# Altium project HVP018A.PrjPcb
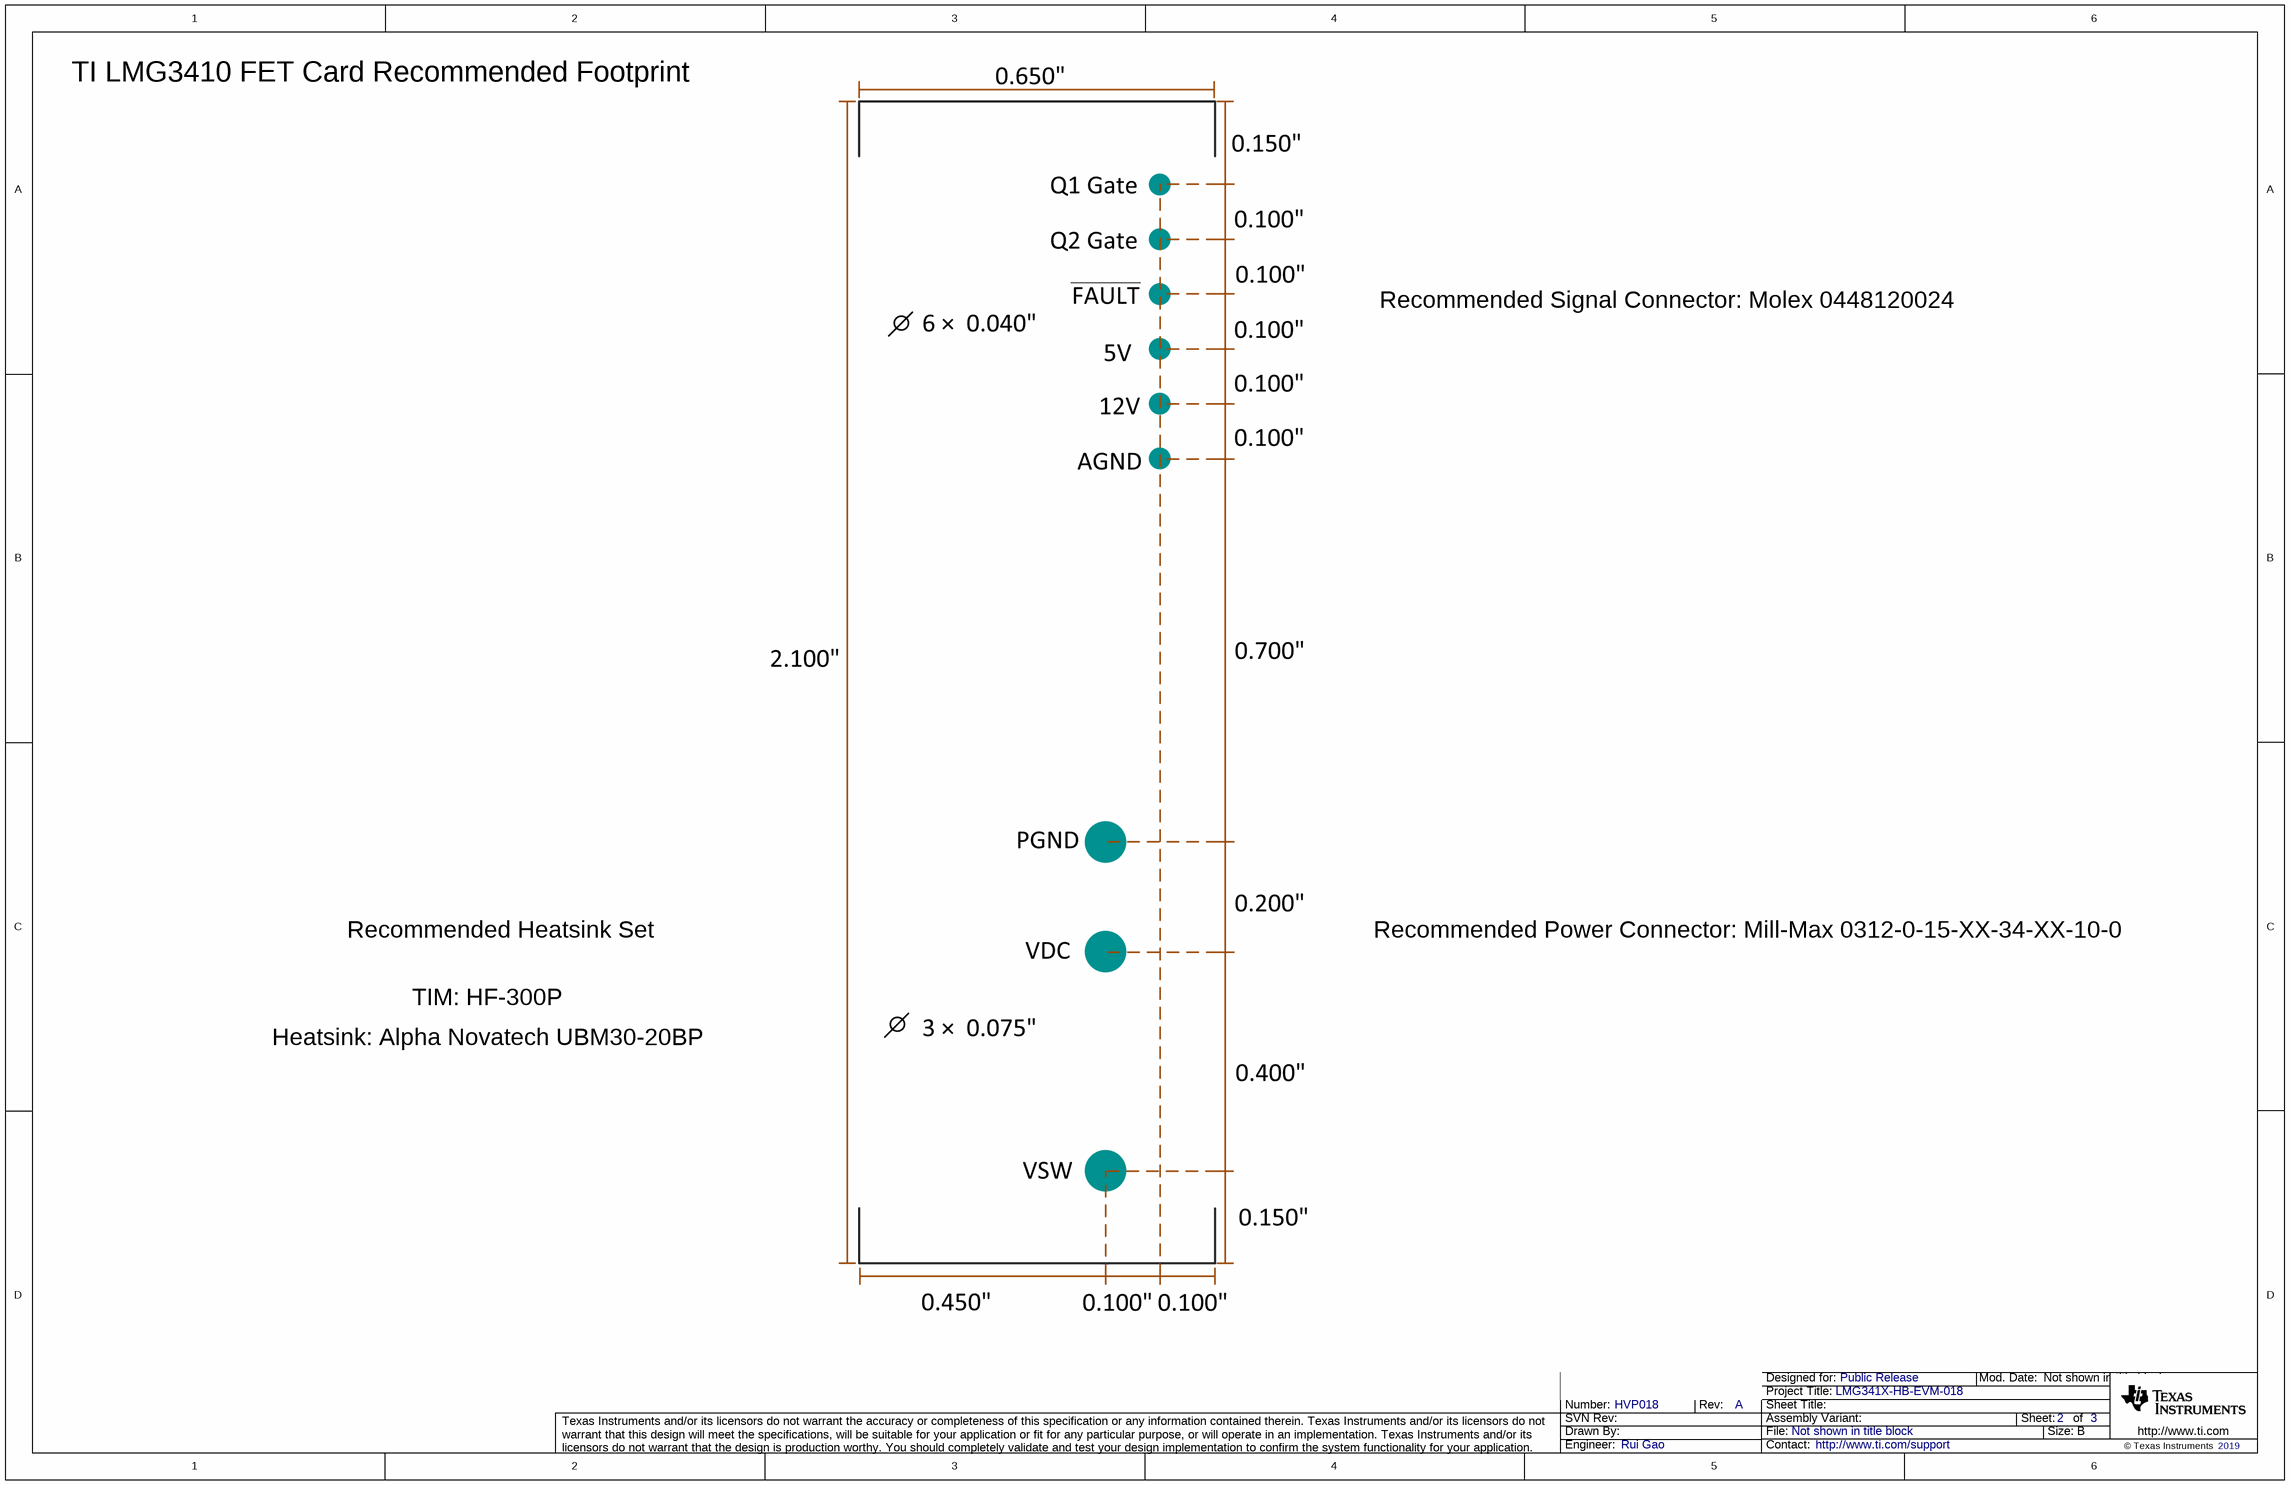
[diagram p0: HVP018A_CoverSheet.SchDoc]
CopyrightYear: 2019; PCB_Layout: Rui Gao; PCB_Rev: A; PRJ_Customer: Public Release; PRJ_Engineer: Rui Gao; PRJ_Number: HVP018; PRJ_Title: LMG341X-HB-EVM-018; SCH_Rev: A; TechSupport: http://www.ti.com/support; TID: N/A
3 sheets, 98 parts. Net scope: global (net labels, ports and power ports of the same name join across sheets).
Board file: HVP018A.PcbDoc
Sheets:
  HVP018A_CoverSheet.SchDoc
  HVP018A_DC.SchDoc
  HVP018A_Hardware.SchDoc

## Sheet HVP018A_CoverSheet.SchDoc
size 431 x 279 mm; Date: Not shown in title block; ApprovedBy: Not shown in title block; CheckedBy: Not shown in title block; Author: Not shown in title block; CompanyName: Not shown in title block; Engineer: Not shown in title block; Organization: Not shown in title block; Address1: Not shown in title block; Address2: Not shown in title block; Address3: Not shown in title block; Address4: Not shown in title block; DocumentNumber: 1; Revision: Use project parameter SCH_Rev; SheetNumber: 2; SheetTotal: 3; PageSetup: Record=PageOptions¦CenterHorizontal=True¦CenterVertical=True¦PrintScale=1.00¦XCorrection=1.00¦YCorrection=1.00¦PrintKind=0¦BorderSize=5000000¦LeftOffset=0¦BottomOffset=0¦Orientation=2¦PaperLength=1000¦PaperWidth=1000¦Scale=100¦PaperSource=15¦PrintQuality=600¦MediaType=1¦DitherType=10¦PaperKind=Letter¦PrintScaleMode=1

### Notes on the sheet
- TI LMG3410 FET Card Recommended Footprint
- Recommended Signal Connector: Molex 0448120024
- Recommended Heatsink Set
- Recommended Power Connector: Mill-Max 0312-0-15-XX-34-XX-10-0
- TIM: HF-300P
- Heatsink: Alpha Novatech UBM30-20BP

## Sheet HVP018A_DC.SchDoc
size 431 x 279 mm; Date: Not shown in title block; ApprovedBy: Not shown in title block; CheckedBy: Not shown in title block; Author: Not shown in title block; CompanyName: Not shown in title block; Engineer: Not shown in title block; Organization: Not shown in title block; Address1: Not shown in title block; Address2: Not shown in title block; Address3: Not shown in title block; Address4: Not shown in title block; DocumentNumber: 1; Revision: Use project parameter SCH_Rev; SheetNumber: 1; SheetTotal: 1; PageSetup: Record=PageOptions¦CenterHorizontal=True¦CenterVertical=True¦PrintScale=0.62¦XCorrection=1.00¦YCorrection=1.00¦PrintKind=0¦BorderSize=5000000¦LeftOffset=0¦BottomOffset=0¦Orientation=2¦PaperLength=1000¦PaperWidth=1000¦Scale=100¦PaperSource=15¦PrintQuality=600¦MediaType=1¦DitherType=10¦PrintScaleMode=1¦PaperKind=Letter
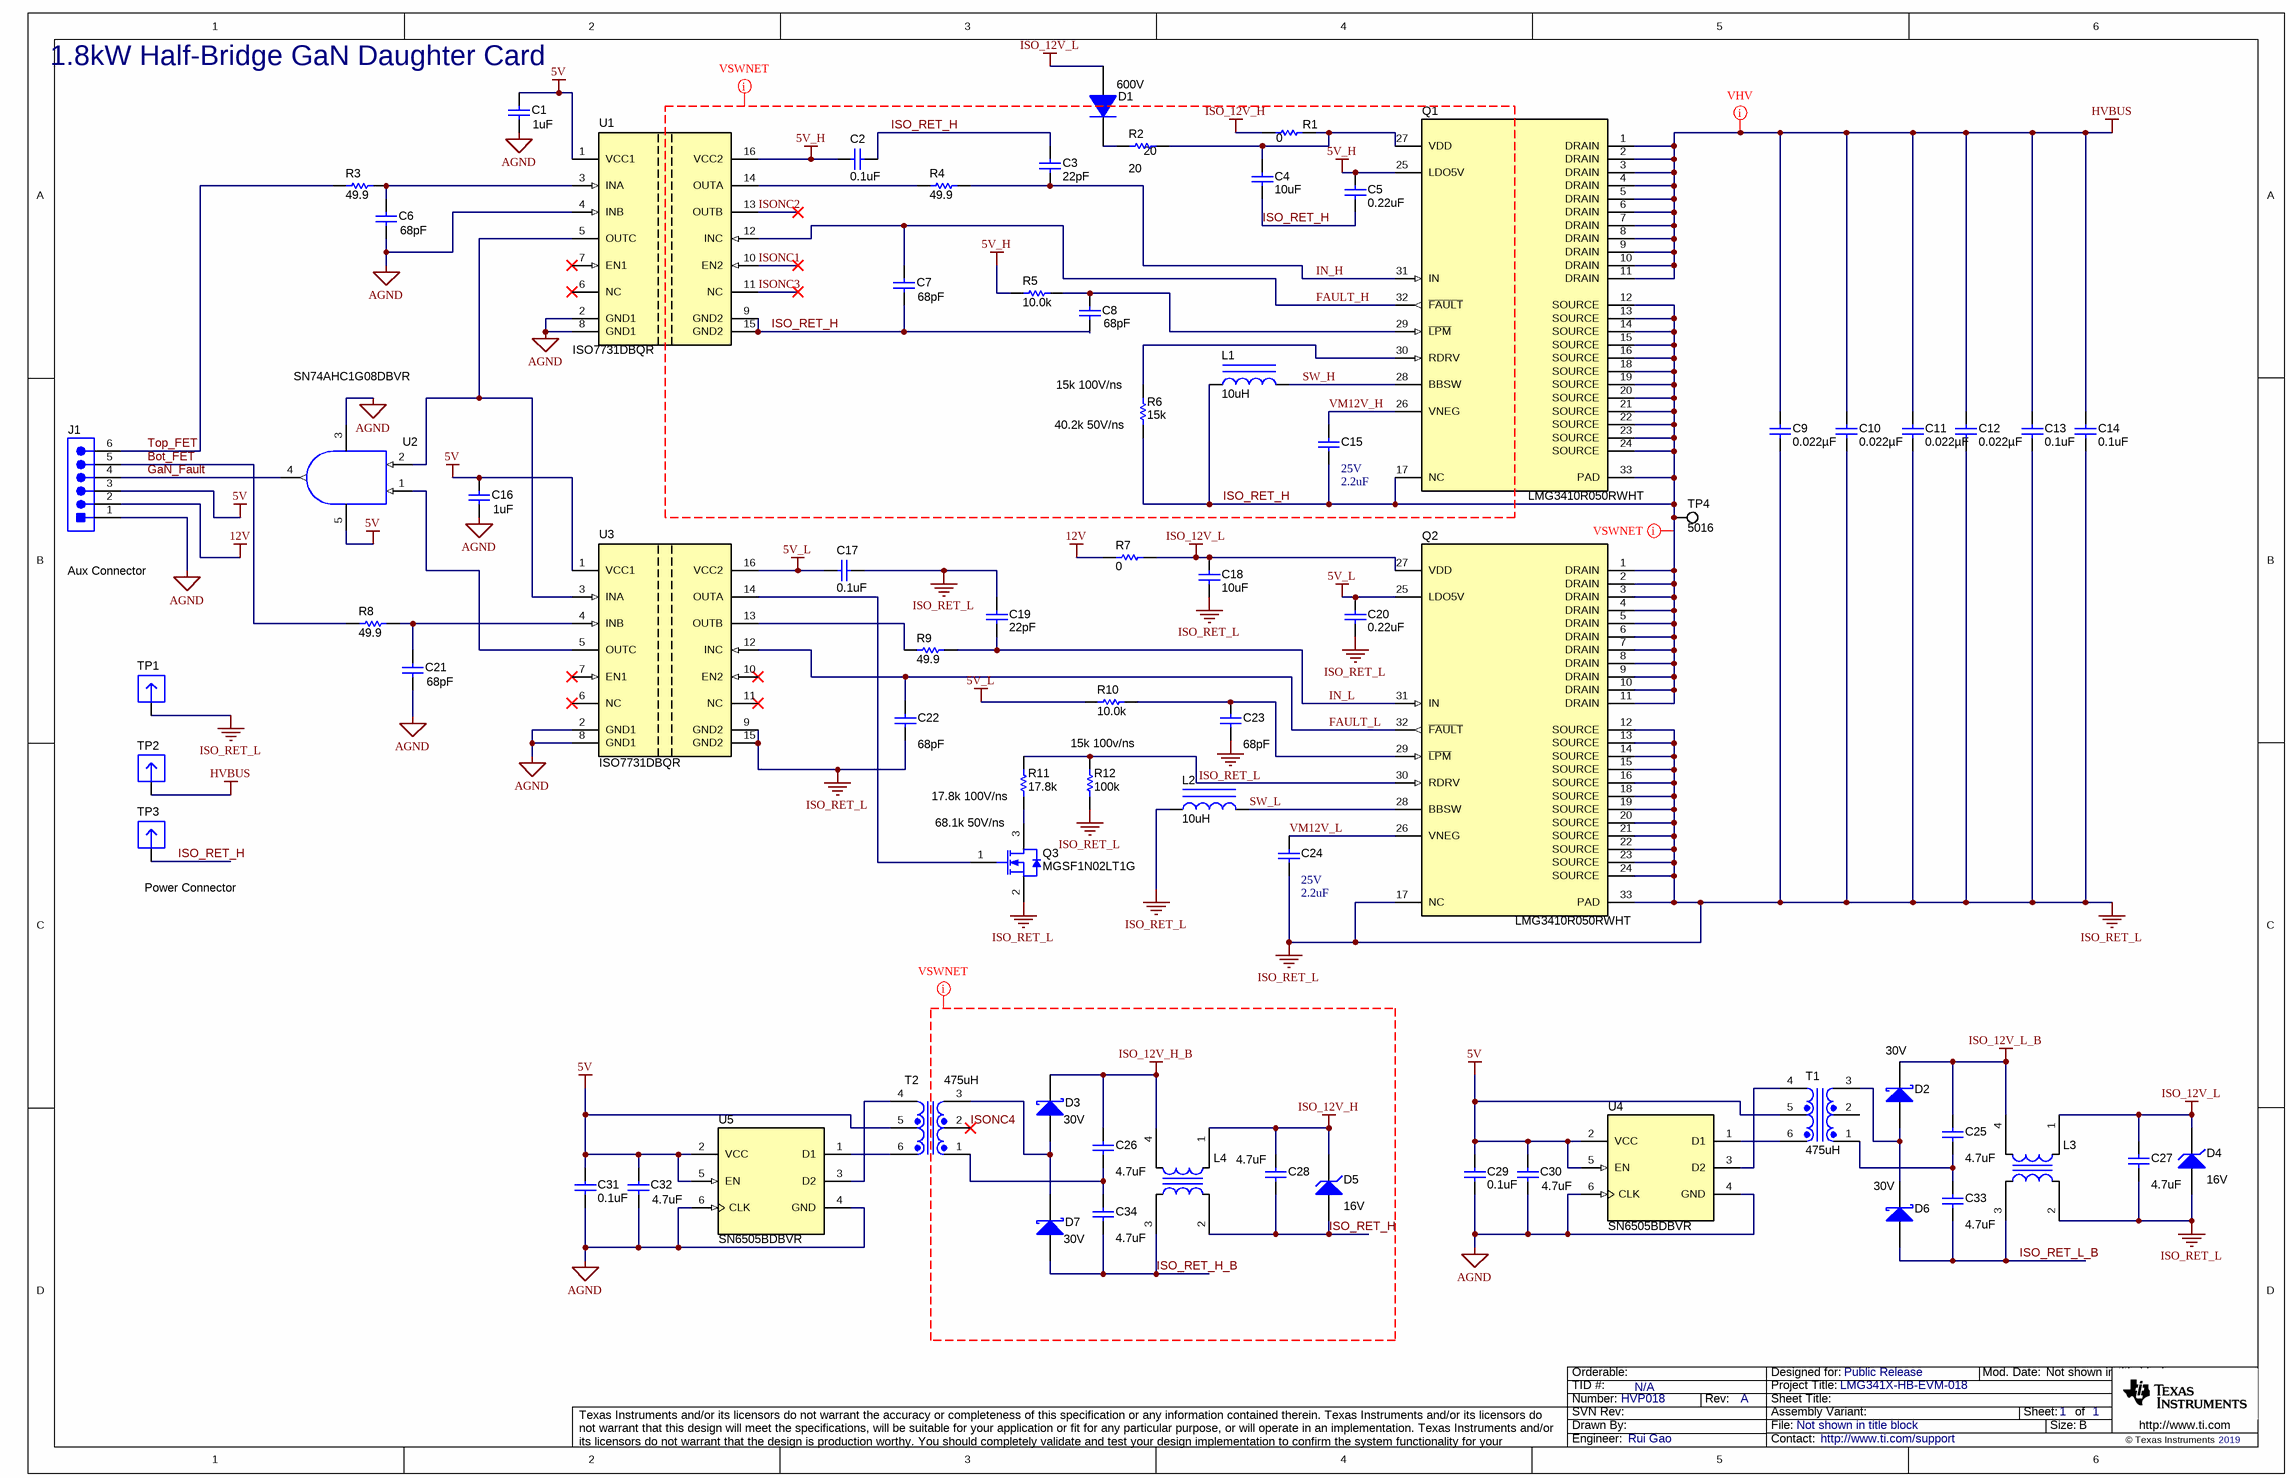
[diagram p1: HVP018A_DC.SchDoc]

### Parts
C1  ValueDisplayed: 1uF  [0402]  (hidden comment: C1005X5R1E105K050BC)
C2  ValueDisplayed: 0.1uF  [0402]  (hidden comment: C1005X7R1H104K050BB)
C3  ValueDisplayed: 22pF  [0402]  (hidden comment: C1005C0G1H220J050BA)
C4  ValueDisplayed: 10uF  [1206_190]  (hidden comment: C1206C106K3RACTU)
C5  ValueDisplayed: 0.22uF  [0603]  (hidden comment: C1608X7R1H224K080AB)
C6  ValueDisplayed: 68pF  [0402]  (hidden comment: C1005C0G1H680J050BA)
C7  ValueDisplayed: 68pF  [0402]  (hidden comment: C1005C0G1H680J050BA)
C8  ValueDisplayed: 68pF  [0402]  (hidden comment: C1005C0G1H680J050BA)
C9  ValueDisplayed: 0.022µF  [1206_190]  (hidden comment: C1206C223KDRACTU)
C10  ValueDisplayed: 0.022µF  [1206_190]  (hidden comment: C1206C223KDRACTU)
C11  ValueDisplayed: 0.022µF  [1206_190]  (hidden comment: C1206C223KDRACTU)
C12  ValueDisplayed: 0.022µF  [1206_190]  (hidden comment: C1206C223KDRACTU)
C13  ValueDisplayed: 0.1uF  [1812_254]  (hidden comment: C1812W104KDRACTU)
C14  ValueDisplayed: 0.1uF  [1812_254]  (hidden comment: C1812W104KDRACTU)
C15  VDC_V: 25V  ValueDisplayed: 2.2uF  [0805_HV]  (hidden comment: GRM219R61E225KA12D)
C16  ValueDisplayed: 1uF  [0402]  (hidden comment: C1005X5R1E105K050BC)
C17  ValueDisplayed: 0.1uF  [0402]  (hidden comment: C1005X7R1H104K050BB)
C18  ValueDisplayed: 10uF  [1206_190]  (hidden comment: C1206C106K3RACTU)
C19  ValueDisplayed: 22pF  [0402]  (hidden comment: C1005C0G1H220J050BA)
C20  ValueDisplayed: 0.22uF  [0603]  (hidden comment: C1608X7R1H224K080AB)
C21  ValueDisplayed: 68pF  [0402]  (hidden comment: C1005C0G1H680J050BA)
C22  ValueDisplayed: 68pF  [0402]  (hidden comment: C1005C0G1H680J050BA)
C23  ValueDisplayed: 68pF  [0402]  (hidden comment: C1005C0G1H680J050BA)
C24  VDC_V: 25V  ValueDisplayed: 2.2uF  [0805_HV]  (hidden comment: GRM219R61E225KA12D)
C25  ValueDisplayed: 4.7uF  [0603]  (hidden comment: C1608X5R1V475K080AC)
C26  ValueDisplayed: 4.7uF  [0603]  (hidden comment: C1608X5R1V475K080AC)
C27  ValueDisplayed: 4.7uF  [0603]  (hidden comment: C1608X5R1V475K080AC)
C28  ValueDisplayed: 4.7uF  [0603]  (hidden comment: C1608X5R1V475K080AC)
C29  ValueDisplayed: 0.1uF  [0402]  (hidden comment: C1005X7R1H104K050BB)
C30  ValueDisplayed: 4.7uF  [0805_HV]  (hidden comment: GCM21BR71C475KA73L)
C31  ValueDisplayed: 0.1uF  [0402]  (hidden comment: C1005X7R1H104K050BB)
C32  ValueDisplayed: 4.7uF  [0805_HV]  (hidden comment: GCM21BR71C475KA73L)
C33  ValueDisplayed: 4.7uF  [0603]  (hidden comment: C1608X5R1V475K080AC)
C34  ValueDisplayed: 4.7uF  [0603]  (hidden comment: C1608X5R1V475K080AC)
D1  value 600V  [SOD-123FL]  (hidden comment: UFM15PL-TP)
D2  value 30V  [SOD-123]  (hidden comment: B0530W-7-F)
D3  value 30V  [SOD-123]  (hidden comment: B0530W-7-F)
D4  value 16V  [SOD-123]  (hidden comment: BZT52C16-7-F)
D5  value 16V  [SOD-123]  (hidden comment: BZT52C16-7-F)
D6  value 30V  [SOD-123]  (hidden comment: B0530W-7-F)
D7  value 30V  [SOD-123]  (hidden comment: B0530W-7-F)
J1  90121-0766  [Molex_90121-0766]  (value not drawn)
L1  ValueDisplayed: 10uH  [WE-LQS_2010]  (hidden comment: 74404020100)
L2  ValueDisplayed: 10uH  [WE-LQS_2010]  (hidden comment: 74404020100)
L3  ACM2520-601-2P-T002  [TDK_ACM2520-2P]  (value not drawn)
L4  ACM2520-601-2P-T002  [TDK_ACM2520-2P]  (value not drawn)
Q1  LMG3410R050RWHT  [RWH0032A_NV]
Q2  LMG3410R050RWHT  [RWH0032A_NV]
Q3  MGSF1N02LT1G  [SOT-23]
R1  ValueDisplayed: 0  [0603]  (hidden comment: MCT06030Z0000ZP500)
R2  value 20  [0603]  (hidden comment: CRCW060320R0JNEA)
R3  ValueDisplayed: 49.9  [0402]  (hidden comment: RC0402FR-0749R9L)
R4  ValueDisplayed: 49.9  [0402]  (hidden comment: RC0402FR-0749R9L)
R5  ValueDisplayed: 10.0k  [0402]  (hidden comment: ERJ-2RKF1002X)
R6  ValueDisplayed: 15k  [0402]  (hidden comment: CRCW040215K0JNED)
R7  ValueDisplayed: 0  [2512]  (hidden comment: CRCW25120000Z0EG)
R8  ValueDisplayed: 49.9  [0402]  (hidden comment: RC0402FR-0749R9L)
R9  ValueDisplayed: 49.9  [0402]  (hidden comment: RC0402FR-0749R9L)
R10  ValueDisplayed: 10.0k  [0402]  (hidden comment: ERJ-2RKF1002X)
R11  ValueDisplayed: 17.8k  [0402]  (hidden comment: CRCW040217K8FKED)
R12  ValueDisplayed: 100k  [0402]  (hidden comment: RC1005F104CS)
T1  ValueDisplayed: 475uH  [Wurth_760390013]  (hidden comment: 760390014)
T2  ValueDisplayed: 475uH  [Wurth_760390013]  (hidden comment: 760390014)
TP1  3620-2-32-15-00-00-08-0  [Mill-Max_3620-2-32-xx-00-00-08-0]  (value not drawn)
TP2  3620-2-32-15-00-00-08-0  [Mill-Max_3620-2-32-xx-00-00-08-0]  (value not drawn)
TP3  3620-2-32-15-00-00-08-0  [Mill-Max_3620-2-32-xx-00-00-08-0]  (value not drawn)
TP4  5016  [Testpoint_Keystone_Compact]
U1  ISO7731DBQR  [DBQ0016A_N]
U2  SN74AHC1G08DBVR  [DBV0005A_N]
U3  ISO7731DBQR  [DBQ0016A_N]
U4  SN6505BDBVR  [DBV0006A_N]
U5  SN6505BDBVR  [DBV0006A_N]

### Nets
5V: C1.1 C16.1 C29.1 C30.1 C31.1 C32.1 J1.3 T1.5 T2.5 U1.1(VCC1) U2.5(V+) U3.1(VCC1) U4.2(VCC) U4.5(EN) U5.2(VCC) U5.5(EN)
5V_H: C2.2 C5.1 Q1.25(LDO5V) R5.1 U1.16(VCC2)
5V_L: C17.2 C20.1 Q2.25(LDO5V) R10.1 U3.16(VCC2)
12V: J1.2 R7.1
AGND: C1.2 C6.2 C16.2 C21.2 C29.2 C30.2 C31.2 C32.2 J1.1 U1.2(GND1) U1.4(INB) U1.8(GND1) U2.3(V-) U3.2(GND1) U3.8(GND1) U4.4(GND) U4.6(CLK) U5.4(GND) U5.6(CLK)
HVBUS: C9.1 C10.1 C11.1 C12.1 C13.1 C14.1 Q1.1(DRAIN) Q1.2(DRAIN) Q1.3(DRAIN) Q1.4(DRAIN) Q1.5(DRAIN) Q1.6(DRAIN) Q1.7(DRAIN) Q1.8(DRAIN) Q1.9(DRAIN) Q1.10(DRAIN) Q1.11(DRAIN) TP2.1
ISO_12V_H: C28.1 D5.1(K) L4.1 R1.1
ISO_12V_H_B: C26.1 D3.1(K) L4.4
ISO_12V_L: C18.1 C27.1 D1.2(A) D4.1(K) L3.1 Q2.27(VDD) R7.2
ISO_12V_L_B: C25.1 D2.1(K) L3.4
ISO_RET_L: C9.2 C10.2 C11.2 C12.2 C13.2 C14.2 C17.1 C18.2 C19.1 C20.2 C22.2 C23.2 C24.2 C27.2 D4.2(A) L2.1 L3.2 Q2.12(SOURCE) Q2.13(SOURCE) Q2.14(SOURCE) Q2.15(SOURCE) Q2.16(SOURCE) Q2.17(NC) Q2.18(SOURCE) Q2.19(SOURCE) Q2.20(SOURCE) Q2.21(SOURCE) Q2.22(SOURCE) Q2.23(SOURCE) Q2.24(SOURCE) Q2.33(PAD) Q3.2(S) R12.1 TP1.1 U3.9(GND2) U3.15(GND2)
Bot_FET: J1.5 R8.1
FAULT_H: C7.1 Q1.32(~{FAULT}) U1.12(INC)
FAULT_L: C22.1 Q2.32(~{FAULT}) U3.12(INC)
GaN_Fault: J1.4 U2.4(Y)
IN_H: C3.2 Q1.31(IN) R4.2
IN_L: C19.2 Q2.31(IN) R9.2
ISO_RET_H: C2.1 C3.1 C4.2 C5.2 C7.2 C8.2 C15.2 C28.2 D5.2(A) L1.1 L4.2 Q1.12(SOURCE) Q1.13(SOURCE) Q1.14(SOURCE) Q1.15(SOURCE) Q1.16(SOURCE) Q1.17(NC) Q1.18(SOURCE) Q1.19(SOURCE) Q1.20(SOURCE) Q1.21(SOURCE) Q1.22(SOURCE) Q1.23(SOURCE) Q1.24(SOURCE) Q1.33(PAD) Q2.1(DRAIN) Q2.2(DRAIN) Q2.3(DRAIN) Q2.4(DRAIN) Q2.5(DRAIN) Q2.6(DRAIN) Q2.7(DRAIN) Q2.8(DRAIN) Q2.9(DRAIN) Q2.10(DRAIN) Q2.11(DRAIN) R6.1 TP3.1 TP4.1 U1.9(GND2) U1.15(GND2)
ISO_RET_H_B: C34.2 D7.2(A) L4.3
ISO_RET_L_B: C33.2 D6.2(A) L3.3
ISONC1: U1.10(EN2)
ISONC2: U1.13(OUTB)
ISONC3: U1.11(NC)
ISONC4: T2.2
SW_H: L1.2 Q1.28(BBSW)
SW_L: L2.2 Q2.28(BBSW)
Top_FET: J1.6 R3.1
VM12V_H: C15.1 Q1.26(VNEG)
VM12V_L: C24.1 Q2.26(VNEG)
NetC4_1: C4.1 Q1.27(VDD) R1.2 R2.2
NetC6_1: C6.1 R3.2 U1.3(INA)
NetC8_1: C8.1 Q1.29(~{LPM}) R5.2
NetC21_1: C21.1 R8.2 U3.4(INB)
NetC23_1: C23.1 Q2.29(~{LPM}) R10.2
NetC25_2: C25.2 C33.1 T1.1
NetC26_2: C26.2 C34.1 T2.1
NetD1_1: D1.1(K) R2.1
NetD2_2: D2.2(A) D6.1(K) T1.3
NetD3_2: D3.2(A) D7.1(K) T2.3
NetQ1_30: Q1.30(RDRV) R6.2
NetQ2_30: Q2.30(RDRV) R11.2 R12.2
NetQ3_1: Q3.1(G) U3.14(OUTA)
NetQ3_3: Q3.3(D) R11.1
NetR4_1: R4.1 U1.14(OUTA)
NetR9_1: R9.1 U3.13(OUTB)
NetT1_4: T1.4 U4.3(D2)
NetT1_6: T1.6 U4.1(D1)
NetT2_4: T2.4 U5.3(D2)
NetT2_6: T2.6 U5.1(D1)
NetU1_5: U1.5(OUTC) U2.2(B) U3.3(INA)
NetU2_1: U2.1(A) U3.5(OUTC)

Not connected (* = marked no-connect by the designer): T1 2; U1 6(NC)* 7(EN1)*; U3 6(NC)* 7(EN1)* 10(EN2)* 11(NC)*

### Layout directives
net class VSWNET: 5V_H, FAULT_H, IN_H, ISO_12V_H, ISO_12V_H_B, ISO_RET_H, ISO_RET_H_B, ISONC1, ISONC2, ISONC3, ISONC4, SW_H, VM12V_H
net class VHV: HVBUS

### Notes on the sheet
- (near C1) 1.8kW Half-Bridge GaN Daughter Card
- (near R6) 15k 100V/ns
- (near R6) 40.2k 50V/ns
- (near J1) Aux Connector
- (near R12) 15k 100v/ns
- (near R11) 17.8k 100V/ns
- 68.1k 50V/ns
- (near TP3) Power Connector

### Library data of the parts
C1 C16 = CMP-0006276-2: CAP, CERM, 1 uF, 25 V, +/- 10%, X5R, 0402; Manufacturer: TDK; Alternate PartNumber: C1005X5R1E225K050BC; TaMin_C: -55°C; Polarized: N; SizeAreaWB_mm2: 3; Value1: Unknown; U/M: EA; Value: 1uF; TaMax_C: 80°C; SizeZ_mm: 0.6; SizeX_mm: 1; SizeY_mm: 0.5; Value2: 25V; CompType: Capacitor; Cap_F: 1µF; AEC Category: Q200
C2 C17 = CMP-0006297-2: CAP, CERM, 0.1 uF, 50 V, +/- 10%, X7R, 0402; Manufacturer: TDK; Alternate PartNumber: 885012205037; Alternate Manufacturer: Wurth Elektronik; Polarized: N; Value: 0.1uF; U/M: EA; Cap_F: 100nF; ESR_ohm: 0.039064; Value1: 0.039064 ohm; VDC_V: 50V; IRMS_A: 8.14669dA; TaMin_C: -55°C; TaMax_C: 125°C; SizeArea_mm2: 0.5; SizeAreaWB_mm2: 3; SizeX_mm: 1; SizeZ_mm: 0.6; AEC Category: Q200
C3 C19 = CMP-0006248-2: CAP, CERM, 22 pF, 50 V, +/- 5%, C0G/NP0, 0402; Manufacturer: TDK; Alternate PartNumber: CGA2B2NP01H220J050BA; Polarized: N; Value: 22pF; U/M: EA; Value1: Unknown; VDC_V: 50V; TaMin_C: -55°C; TaMax_C: 125°C; AEC Category: Q200; SizeArea_mm2: 0.5; SizeAreaWB_mm2: 3; SizeX_mm: 1; SizeZ_mm: 0.6
C4 C18 = CMP-0008589-2: CAP, CERM, 10 uF, 25 V, +/- 10%, X7R, 1206_190; Manufacturer: Kemet; Polarized: N; Value: 10uF; U/M: EA; Cap_F: 10µF; Value1: Unknown; VDC_V: 25V; TaMin_C: -55°C; TaMax_C: 125°C; Cap_Case: 1206; SizeArea_mm2: 5.12; SizeAreaWB_mm2: 10.92; SizeX_mm: 3.2; SizeY_mm: 1.6; SizeZ_mm: 1.9; AEC Category: Q200
C5 C20 = CMP-0007047-4: CAP, CERM, 0.22 uF, 50 V, +/- 10%, X7R, 0603; Manufacturer: TDK; Alternate PartNumber: C0603C224J3RAC7867; Alternate Manufacturer: Kemet; Polarized: N; Value: 0.22uF; U/M: EA; Cap_F: 220nF; ESR_ohm: 0.021699; Value1: 0.021699 ohm; VDC_V: 50V; IRMS_A: 1.12496A; TaMin_C: -55°C; TaMax_C: 125°C; AEC Category: Q200; SizeArea_mm2: 1.28; SizeAreaWB_mm2: 4.68; SizeX_mm: 1.6; SizeY_mm: 0.8; SizeZ_mm: 1
C6-C8 C21-C23 = CMP-0006251-2: CAP, CERM, 68 pF, 50 V, +/- 5%, C0G/NP0, 0402; Manufacturer: TDK; Alternate Manufacturer: Murata; Alternate PartNumber: GRM1555C1H680JA01D; TaMin_C: -55°C; Polarized: N; SizeAreaWB_mm2: 3; Value1: Unknown; U/M: EA; Value: 68pF; TaMax_C: 125°C; SizeZ_mm: 0.6; SizeX_mm: 1; SizeY_mm: 0.5; Value2: 50V; AEC Category: Q200
C9-C12 = CMP-0084048-1: CAP, CERM, 0.022 µF, 1000 V,+/- 10%, X7R, AEC-Q200 Grade 1, 1206; Manufacturer: Kemet; Polarized: N; CompType: Capacitor; Value: 0.022uF; U/M: EA; Cap_F: 22nF; VDC_V: 1kV; Value2: 1000V; TaMin_C: -55°C; TaMax_C: 125°C; Cap_Case: 1206; SizeArea_mm2: 5.12; SizeAreaWB_mm2: 10.92; SizeX_mm: 3.2; SizeY_mm: 1.6; SizeZ_mm: 1.9; AEC Category: Q200; AEC Qualified: Y; AEC Grade: 1
C13 C14 = CMP-0009326-2: CAP, CERM, 0.1 uF, 1000 V, +/- 10%, X7R, 1812; Manufacturer: Kemet; Polarized: N; Value: 0.1uF; U/M: EA; Cap_F: 100nF; Value1: Unknown; VDC_V: 1kV; Value2: 1000V; TaMin_C: -55°C; TaMax_C: 125°C; Cap_Case: 1812; AEC Category: Q200; SizeArea_mm2: 14.4; SizeAreaWB_mm2: 23.1; SizeX_mm: 4.5; SizeY_mm: 3.2; SizeZ_mm: 2.54
C15 C24 = CMP-0008208-1: CAP, CERM, 2.2 uF, 25 V, +/- 10%, X5R, 0805; Manufacturer: MuRata; TaMin_C: -55°C; ESR_ohm: 6m; Polarized: N; SizeAreaWB_mm2: 6.75; Value1: 0.006 ohm; U/M: EA; Value: 2.2uF; TaMax_C: 85°C; SizeZ_mm: 1.45; SizeX_mm: 2; SizeY_mm: 1.25; Cap_Case: 0805; SizeArea_mm2: 2.5; Cap_F: 2.2µF; AEC Category: Q200
C25 C27 C28 C33 = CMP-0007022-5: CAP, CERM, 4.7 uF, 35 V, +/- 10%, X5R, 0603; Manufacturer: TDK; TaMin_C: -55°C; ESR_ohm: 3.728m; Polarized: N; SizeAreaWB_mm2: 4.68; Value1: 0.003728 ohm; U/M: EA; Value: 4.7uF; TaMax_C: 85°C; SizeZ_mm: 1; SizeX_mm: 1.6; SizeY_mm: 0.8; Value2: 35V; SizeArea_mm2: 1.28; Cap_F: 4.7µF; IRMS_A: 2.69359A; AEC Category: Q200
C26 C34 = CMP-0007022-5: CAP, CERM, 4.7 uF, 35 V, +/- 10%, X5R, 0603; Manufacturer: TDK; TaMin_C: -55°C; ESR_ohm: 3.728m; Polarized: N; SizeAreaWB_mm2: 4.68; Value1: 0.003728 ohm; U/M: EA; Value: 4.7uF; TaMax_C: 85°C; SizeZ_mm: 1; SizeX_mm: 1.6; SizeY_mm: 0.8; Value2: 35V; SizeArea_mm2: 1.28; CompType: Capacitor; Cap_F: 4.7µF; IRMS_A: 2.69359A; AEC Category: Q200
C29 = CMP-0006297-2: CAP, CERM, 0.1 uF, 50 V, +/- 10%, X7R, 0402; Manufacturer: TDK; Alternate PartNumber: 885012205037; Alternate Manufacturer: Wurth Elektronik; Polarized: N; Value: 0.1uF; U/M: EA; Cap_F: 100nF; ESR_ohm: 0.039064; Value1: 0.039064 ohm; VDC_V: 50V; IRMS_A: 8.14669dA; TaMin_C: -55°C; TaMax_C: 125°C; AEC Category: Q200; SizeArea_mm2: 0.5; SizeAreaWB_mm2: 3; SizeX_mm: 1; SizeZ_mm: 0.6
C30 C32 = CMP-0008020-2: CAP, CERM, 4.7 uF, 16 V, +/- 10%, X7R, AEC-Q200 Grade 1, 0805; Manufacturer: MuRata; TaMin_C: -55°C; Polarized: N; SizeAreaWB_mm2: 6.75; Value1: Unknown; U/M: EA; Value: 4.7uF; TaMax_C: 125°C; SizeZ_mm: 1.45; SizeX_mm: 2; SizeY_mm: 1.25; Cap_Case: 0805; Value2: 16V; SizeArea_mm2: 2.5; AEC Qualified: Y; Cap_F: 4.7µF; AEC Grade: 1; AEC Category: Q200
C31 = CMP-0006297-2: CAP, CERM, 0.1 uF, 50 V, +/- 10%, X7R, 0402; Manufacturer: TDK; Alternate PartNumber: 885012205037; Alternate Manufacturer: Wurth Elektronik; Polarized: N; CompType: Capacitor; Value: 0.1uF; U/M: EA; Cap_F: 100nF; ESR_ohm: 0.039064; Value1: 0.039064 ohm; VDC_V: 50V; IRMS_A: 8.14669dA; TaMin_C: -55°C; TaMax_C: 125°C; AEC Category: Q200; SizeArea_mm2: 0.5; SizeAreaWB_mm2: 3; SizeX_mm: 1; SizeZ_mm: 0.6
D1 = CMP-0029148-1: Diode, Ultrafast, 600 V, 1 A, SOD-123FL; Manufacturer: Micro Commercial Components; U/M: EA; Vf_V: 1.7V; Value1: 1A; TJmax_C: 150°C; AEC Category: Q101; AEC Qualified: N; SizeAreaWB_mm2: 12.19; SizeArea_mm2: 5.94; SizeX_mm: 3.6; SizeY_mm: 1.65; SizeZ_mm: 0.98; Green_Lifecycle: Not Set; Green_REACh: Incomplete
D2 D3 D6 D7 = CMP-0028643-1: Diode, Schottky, 30 V, 0.5 A, SOD-123; Manufacturer: Diodes Inc.; Io_A: 5dA; Green_Lifecycle: Active; SizeAreaWB_mm2: 13.095; Green_REACh: Passed; Value1: 0.5A; TJmax_C: 125°C; U/M: EA; SizeZ_mm: 1.35; SizeX_mm: 3.85; SizeY_mm: 1.7; Vf_V: 4.3dV; Value2: 0.43V; SizeArea_mm2: 6.545; AEC Category: Q101
D4 D5 = CMP-0005769-2: Diode, Zener, 16 V, 500 mW, AEC-Q101, SOD-123; Manufacturer: Diodes Inc.; Power_W: 500mW; SizeAreaWB_mm2: 13.095; Value1: 0.5W; RJA_CperW: 338; U/M: EA; SizeZ_mm: 1.35; SizeX_mm: 3.85; SizeY_mm: 1.7; SizeArea_mm2: 6.545; AEC Qualified: Y; AEC Category: Q101
J1 = CMP-0055334-1: Header, 2.54mm, 6x1, Gold, R/A, TH; Manufacturer: Molex; Pitch_mm: 2.54; Gender: Male; Shrouded: N; Row_Count: 1; Current_A: 3A; Voltage_V: 350V; Cert_UL: Y; CNHeader: TRUE; CT: FALSE
L1 L2 = CMP-0063789-1: Inductor, 10 uH, 0.5 A, 0.85 ohm, SMD; Manufacturer: Wurth Elektronik; Value: 10uH; Ind_H: 10µH; Imax_A: 5dA; Irms: 0.5A @ 40C rise; Isat: 0.6A @ 30% inductance drop; DCR_ohm: 8.5d; Value2: 0.5A; SizeAreaWB_mm2: 7.8; SizeArea_mm2: 3.2; SizeX_mm: 2; SizeY_mm: 1.6; SizeZ_mm: 1; AEC Category: Q200; AEC Qualified: N
L3 L4 = CMP-0013161-2: Coupled inductor, 0.2 A, 0.45 ohm, SMD; Manufacturer: TDK; DCR_ohm: 4.5d; SizeAreaWB_mm2: 10.5; SizeArea_mm2: 5; SizeX_mm: 2.5; SizeY_mm: 2; SizeZ_mm: 1.3
Q1 Q2 = CMP-0078874-1: 600-V 12-A Single Channel GaN Power Stage, RWH0032A (VQFN-32); Alternate PartNumber: LMG3410R050RWHR; Alternate Manufacturer: Texas Instruments; SizeAreaWB_mm2: 100; SizeZ_mm: 0.9; SizeX_mm: 8; SizeArea_mm2: 64; CompType: IC; AEC Qualified: N; AEC Category: Q200
Q3 = CMP-0000221-1: MOSFET, N-CH, 20 V, 0.75 A, SOT-23; Manufacturer: ON Semiconductor; Alternate Manufacturer: None; U/M: EA; ChType: N; Value: 20V; Value1: 0.1; Rdson45_ohm: 1.3d; Value2: 6 nC; QgTyp_nC: 6; IdsMax_A: 7.5dA; SizeAreaWB_mm2: 14; SizeArea_mm2: 7.5; SizeX_mm: 2.5; SizeY_mm: 3; SizeZ_mm: 1.1; AEC Category: Q101
R1 = CMP-0025884-3: RES, 0, 5%, 0.125 W, 0603; Manufacturer: Vishay/Beyschlag; Power_W: 125mW; TempCo: ppm/C; Value_Code: 0000; U/M: EA; Value: 0; EIA_Code: E24; SizeX_mm: 1.6; SizeY_mm: 0.8; SizeZ_mm: 1; Value2: 0.125W; SizeArea_mm2: 1.28; CompType: Resistor; AEC Qualified: N; AEC Category: Q200
R2 = CMP-0025754-4: RES, 20, 5%, 0.1 W, AEC-Q200 Grade 0, 0603; Manufacturer: Vishay-Dale; CompType: Resistor; Value_Code: 20R0; Power_W: 100mW; Value2: 0.1W; VDC_V: 75V; TempCo: 200 ppm/C; EIA_Code: E24; SizeArea_mm2: 1.28; SizeX_mm: 1.6; SizeY_mm: 0.8; SizeZ_mm: 1; AEC Category: Q200; AEC Qualified: Y; AEC Grade: 0
R3 R4 R8 R9 = CMP-0026738-1: RES, 49.9, 1%, 0.063 W, 0402; Manufacturer: Yageo America; Value: 49.9; Value_Code: 49R9; Power_W: 63mW; Value2: 0.063W; VDC_V: 50V; TempCo: 100 ppm/C; EIA_Code: E96; U/M: EA; AEC Category: Q200; AEC Qualified: N; SizeArea_mm2: 0.5; SizeX_mm: 1; SizeZ_mm: 0.6
R5 R10 = CMP-0026658-1: RES, 10.0 k, 1%, 0.1 W, 0402; Manufacturer: Panasonic; Value: 10.0k; Res_ohm: 10k; Value_Code: 10k0; Power_W: 100mW; Value2: 0.1W; VDC_V: 50V; TempCo: 100 ppm/C; EIA_Code: E96; U/M: EA; AEC Category: Q200; SizeArea_mm2: 0.5; SizeX_mm: 1; SizeZ_mm: 0.6
R6 = CMP-0026842-3: RES, 15 k, 5%, 0.063 W, AEC-Q200 Grade 0, 0402; Manufacturer: Vishay-Dale; Value: 15k; Value_Code: 15k0; Power_W: 63mW; Value2: 0.063W; VDC_V: 50V; TempCo: 200 ppm/C; SizeArea_mm2: 0.5; SizeX_mm: 1; SizeZ_mm: 0.6; EIA_Code: E24; AEC Category: Q200; AEC Qualified: Y; AEC Grade: 0
R7 = CMP-0015864-3: RES, 0, 5%, 1 W, AEC-Q200 Grade 0, 2512; Manufacturer: Vishay-Dale; Value: 0; Value_Code: 0000; Power_W: 1W; TempCo: ppm/C; EIA_Code: E24; SizeArea_mm2: 20.16; SizeX_mm: 6.3; SizeY_mm: 3.2; SizeZ_mm: 0.71; AEC Category: Q200; AEC Qualified: Y
R11 = CMP-0026051-3: RES, 17.8 k, 1%, 0.063 W, AEC-Q200 Grade 0, 0402; Manufacturer: Vishay-Dale; Value: 17.8k; Value_Code: 17k8; Power_W: 63mW; Value2: 0.063W; VDC_V: 50V; TempCo: 100 ppm/C; SizeArea_mm2: 0.5; SizeX_mm: 1; SizeZ_mm: 0.6; EIA_Code: E96; AEC Category: Q200; AEC Qualified: Y; AEC Grade: 0
R12 = CMP-0026745-1: RES, 100 k, 1%, 0.063 W, 0402; Manufacturer: Samsung Electro-Mechanics; Value: 100k; Power_W: 63mW; Value2: 0.063W; VDC_V: 80V; TempCo: 100 ppm/C; EIA_Code: E96; U/M: EA; AEC Category: Q200; AEC Qualified: N; SizeArea_mm2: 0.5; SizeX_mm: 1; SizeZ_mm: 0.6
T1 T2 = CMP-0030718-1: Transformer, 475uH, SMT; Manufacturer: Wurth Elektronik; Lp: 475; DCR_ohm: 3.1d; Ind_H: 475µH
TP1-TP3 = CMP-0055044-1: PCB Pin, 0.04" DIA, Edge-Mount; Manufacturer: Mill-Max; CompType: PCB Pin; Gender: Male; Row_Count: 1; ContactFinish: Gold; CNHeader: FALSE
TP4 = CMP-0055153-1: Test Point, Compact, SMT; Manufacturer: Keystone; CNHeader: FALSE; Green_Lifecycle: Active; Green_REACh: Passed; CT: TRUE
U1 U3 = CMP-0013035-2: High Speed, Robust EMC Reinforced Triple-Channel Digital Isolator, DBQ0016A (SSOP-16); Manufacturer: Texas Instruments; CompType: IC; U/M: EA; SizeArea_mm2: 60; SizeAreaWB_mm2: 96; SizeX_mm: 6; SizeY_mm: 10; SizeZ_mm: 1.75
U2 = CMP-0051578-2: Single 2-Input Positive-AND Gate, DBV0005A (SOT-23-5); Alternate PartNumber: SN74AHC1G08DBVT; Manufacturer: Texas Instruments; CompType: IC; SizeArea_mm2: 8.12; SizeAreaWB_mm2: 14.82; SizeX_mm: 2.8; SizeY_mm: 2.9; SizeZ_mm: 1.45; 3-State Output: No; AEC Category: Q200; AEC Qualified: N; Bits(#): 1; F @ Nom Voltage(Max)(Mhz): 75; Gate Type: AND; ICC @ Nom Voltage(Max)(mA): 0.01; Input Type: CMOS; Logic: True; Output Drive (IOL/IOH)(Max)(mA): 50/-50; Rating: Catalog; Technology Family: AHC; tpd @ Nom Voltage(Max)(ns): 12.3,7.9; VCC(Max)(V): 5.5; VCC(Min)(V): 2; Voltage(Nom)(V): 3.3,5
U4 U5 = CMP-0076095-1: Low-Noise 1 A, 420 kHz Transformer Driver, DBV0006A (SOT-23-6); Alternate PartNumber: SN6505BDBVT; Manufacturer: Texas Instruments; SizeArea_mm2: 8.12; SizeAreaWB_mm2: 14.82; SizeX_mm: 2.8; SizeY_mm: 2.9; SizeZ_mm: 1.45; CompType: IC; U/M: EA; Green_Lifecycle: Active; Green_REACh: Passed

## Sheet HVP018A_Hardware.SchDoc
size 431 x 279 mm; Date: Not shown in title block; ApprovedBy: Not shown in title block; CheckedBy: Not shown in title block; Author: Not shown in title block; CompanyName: Not shown in title block; Engineer: Not shown in title block; Organization: Not shown in title block; Address1: Not shown in title block; Address2: Not shown in title block; Address3: Not shown in title block; Address4: Not shown in title block; DocumentNumber: 1; Revision: Use project parameter SCH_Rev; SheetNumber: 2; SheetTotal: 3; PageSetup: Record=PageOptions¦CenterHorizontal=True¦CenterVertical=True¦PrintScale=1.00¦XCorrection=1.00¦YCorrection=1.00¦PrintKind=0¦BorderSize=5000000¦LeftOffset=0¦BottomOffset=0¦Orientation=2¦PaperLength=1000¦PaperWidth=1000¦Scale=100¦PaperSource=15¦PrintQuality=600¦MediaType=1¦DitherType=10¦PaperKind=Letter¦PrintScaleMode=1
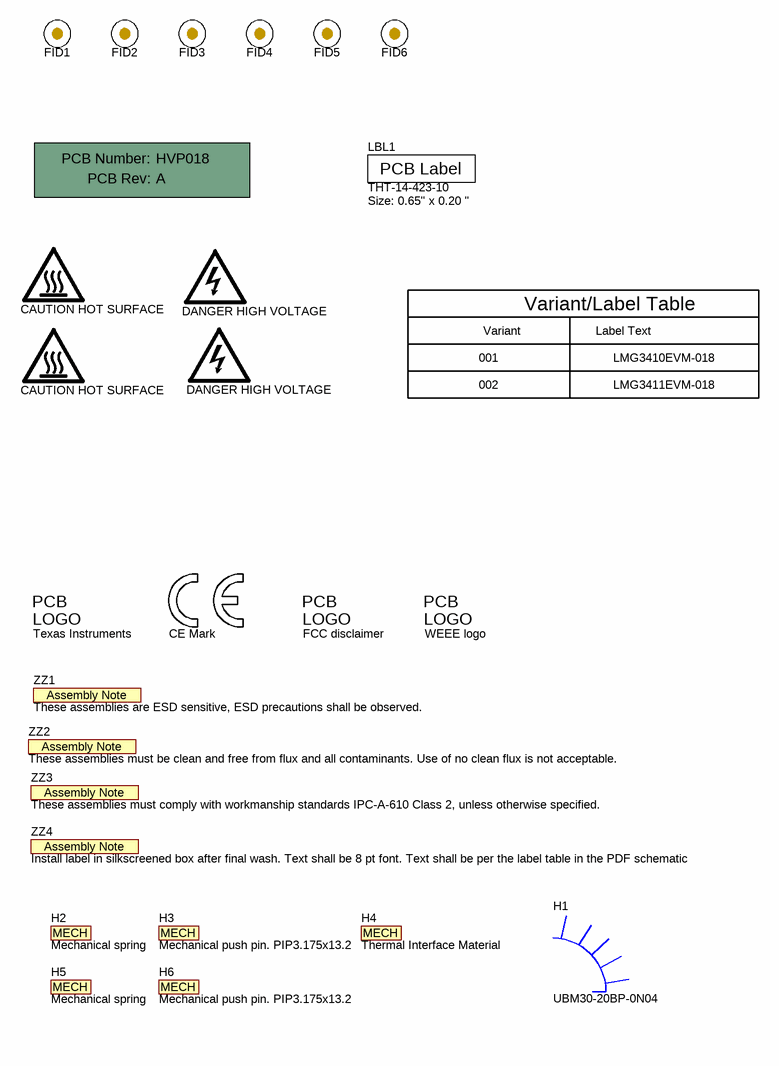
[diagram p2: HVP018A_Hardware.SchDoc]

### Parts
!PCB1  Printed Circuit Board  (value not drawn)  (mechanical)
FID1  Fiducial  [Fiducial6.4-20]  (value not drawn)
FID2  Fiducial  [Fiducial6.4-20]  (value not drawn)
FID3  Fiducial  [Fiducial6.4-20]  (value not drawn)
FID4  Fiducial  [Fiducial6.4-20]  (value not drawn)
FID5  Fiducial  [Fiducial6.4-20]  (value not drawn)
FID6  Fiducial  [Fiducial6.4-20]  (value not drawn)
H1  UBM30-20BP-0N04  (mechanical)
H2  Mechanical spring  (mechanical)
H3  Mechanical push pin. PIP3.175x13.2  (mechanical)
H4  Thermal Interface Material  (mechanical)
H5  Mechanical spring  (mechanical)
H6  Mechanical push pin. PIP3.175x13.2  (mechanical)
LBL1  THT-14-423-10  Note: Size: 0.65" x 0.20 "  [Label_650x200]
LOGO1  CAUTION HOT SURFACE  [IEC_HotSurface_Small]  (no BOM)
LOGO2  DANGER HIGH VOLTAGE  [IEC_HighVoltage_Small]  (no BOM)
LOGO3  CAUTION HOT SURFACE  [IEC_HotSurface_Small]  (no BOM)
LOGO4  DANGER HIGH VOLTAGE  [IEC_HighVoltage_Small]  (no BOM)
Logo5  CE Mark  [CE_Mark_5mm]  (no BOM)
Logo6  Texas Instruments  [TI_Horizontal_Overlay_Small]  (no BOM)
Logo7  FCC disclaimer  [FCC_disclaimer_stacked]  (no BOM)
Logo8  WEEE logo  [WEEE_Minimum]  (no BOM)
ZZ1  These assemblies are ESD sensitive, ESD precautions shall be observed.  [AssemblyNote]  (no BOM)
ZZ2  These assemblies must be clean and free from flux and all contaminants. Use of no clean flux is not acceptable.  [AssemblyNote]  (no BOM)
ZZ3  These assemblies must comply with workmanship standards IPC-A-610 Class 2, unless otherwise specified.  [AssemblyNote]  (no BOM)
ZZ4  Install label in silkscreened box after final wash. Text shall be 8 pt font. Text shall be per the label table in the PDF schematic  [AssemblyNote]  (no BOM)

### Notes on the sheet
- Variant/Label Table
- 001
- Variant
- Label Text
- LMG3410EVM-018
- 002
- LMG3411EVM-018

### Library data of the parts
!PCB1 = CMP-0003618-2: Manufacturer: Any; PartNumber: HVP018
FID1-FID6 = CMP-0077181-1: Fiducial mark.  There is nothing to buy or mount.
H1 = CMP-0079998-1: Heat Sink, Black Anodized, 30 x 30 mm, 20 mm high, with Push Pin and Spring; Manufacturer: Alpha Novatech
H2 H5 = CMP-0080604-2: Mechanical spring. 0.8x6.1x11.2SP; Manufacturer: Alpha Novatech,Inc.; PartNumber: S001YJ08
H3 H6 = CMP-0080604-2: Mechanical push pin; Manufacturer: Alpha Novatech,Inc.; PartNumber: S001YZ1P
H4 = CMP-0080604-2: Manufacturer: Fuji Polymer Industries; PartNumber: 07-62200; CompType: Mechanical
LBL1 = CMP-0003625-1: Thermal Transfer Printable Labels, 0.650" W x 0.200" H - 10,000 per roll; Manufacturer: Brady; CompType: Label
LOGO1 LOGO3 = CMP-0074837-1: IEC 61010-1 Hot Surface Warning; SymbolCreator: a0412235; Lib Reference: IEC_HotSurface
LOGO2 LOGO4 = CMP-0074835-1: IEC 61010-1 High Voltage Warning; SymbolCreator: a0412235; Lib Reference: IEC_HighVoltage
Logo5 = CMP-0074844-1: SymbolCreator: a0412235
Logo6 = CMP-0074838-1: Texas Instrument Corporate Signature; SymbolCreator: a0412235; Lib Reference: TI_Logo; Library Reference: Logo
Logo7 = CMP-0074847-1: FCC_disclaimer; Library Reference: Logo
Logo8 = CMP-0074769-1
ZZ1 = CMP-0077236-1
ZZ2 = CMP-0077237-1
ZZ3 = CMP-0077238-1
ZZ4 = CMP-0077238-1: These assemblies must comply with workmanship standards IPC-A-610 Class 2, unless otherwise specified.

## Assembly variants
001: not fitted D1 FID1 FID2 FID3 FID4 FID5 FID6 R2 R7; alternate parts Q1 -> CMP-0078874-1, Q2 -> CMP-0078874-1
002: not fitted D1 FID1 FID2 FID3 FID4 FID5 FID6 R2 R7; alternate parts Q1 -> CMP-0750036-3, Q2 -> CMP-0750036-3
